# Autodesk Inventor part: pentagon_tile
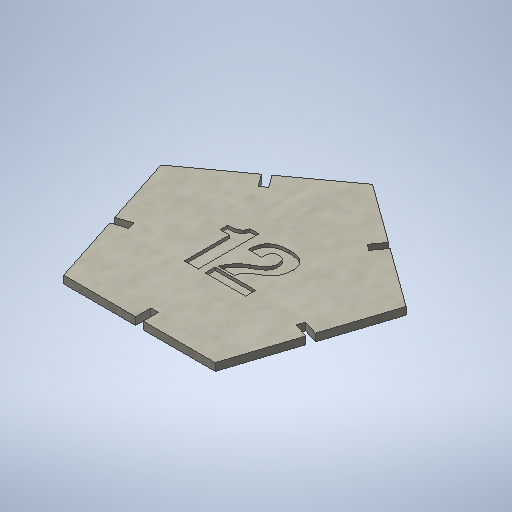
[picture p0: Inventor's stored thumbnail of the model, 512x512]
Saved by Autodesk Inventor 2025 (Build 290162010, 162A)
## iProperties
Created: 2025-02
Part Number: pentagon_tile
Material: Paper
Document SubType Name: Modeling
Designer: BennF
Density: 0.93 g/cm^3
Appearance: Cardboard - Chipboard
Author: BennF
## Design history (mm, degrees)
sketch "Sketch2"
  geometry: L1 (-1.25, -34.41)-(-1.25, -29.41); L2 (-1.25, -29.41)-(1.25, -29.41); L3 (1.25, -29.41)-(1.25, -34.41); L4 (25, -34.41)-(1.25, -34.41); L5 (-1.25, -34.41)-(-25, -34.41); L6 (27.584, -10.277)-(28.356, -7.899); L7 (32.339, -11.822)-(27.584, -10.277); L8 (28.356, -7.899)-(33.112, -9.444); L9 (18.298, 23.058)-(16.275, 24.528); L10 (21.237, 27.103)-(18.298, 23.058); L11 (16.275, 24.528)-(19.214, 28.573); L12 (-16.275, 24.528)-(-18.298, 23.058); L13 (-19.214, 28.573)-(-16.275, 24.528); L14 (-18.298, 23.058)-(-21.237, 27.103); L15 (-28.356, -7.899)-(-27.584, -10.277); L16 (-33.112, -9.444)-(-28.356, -7.899); L17 (-27.584, -10.277)-(-32.339, -11.822); L18 (40.451, 13.143)-(33.112, -9.444); L19 (32.339, -11.822)-(25, -34.41); L20 (0, 42.533)-(19.214, 28.573); L21 (21.237, 27.103)-(40.451, 13.143); L22 (-40.451, 13.143)-(-21.237, 27.103); L23 (-19.214, 28.573)-(0, 42.533); L24 (-25, -34.41)-(-32.339, -11.822); L25 (-33.112, -9.444)-(-40.451, 13.143); 6 further points
  constraints: 50 end point, 3 perpendicular, 2 vertical alignment, 1 collinear, 1 midpoint, 1 vertical, 47 other
  dimensions: "d0" = 50 distance of L4.start L5.end (= pen_side); "d1" = 2.5 distance of L1.end L2.end (= thickness); "d2" = 5 distance of L1.start L1.end (= slot_depth); "d5" = 360 deg dimension on point (0, 0) L1.end (derived)
extrude "Extrusion1" new body sketch "Sketch2" distance "d7" = 2.5 (= thickness); taper "d8" = 0 deg
sketch "Sketch4"
  geometry: L1 (-10, 10)-(10, 10); L2 (10, 10)-(10, -10); L3 (10, -10)-(-10, -10); L4 (-10, -10)-(-10, 10); L5 (-1.25, -29.41)-(1.25, -29.41) reference; 3 further points
  constraints: 2 midpoint, 1 horizontal alignment, 1 parallel, 1 perpendicular, 1 vertical alignment, 2 other
  dimensions: "d9" = 20 distance of L1.start L1.end
emboss "Emboss1" sketch "Sketch4" dims "d10" = 1, "d11" = 0
sketch "laser"
  geometry: L1 (-2.345, -7.041)-(11.013, -7.041) reference; L2 (11.013, -7.041)-(11.013, -10.399) reference; L3 (11.013, -10.399)-(-2.345, -10.399) reference; L4 (-2.345, -10.399)-(-2.345, -7.041) reference; L5 (-7.581, 9.601)-(-4.578, 9.601) reference; L6 (-4.578, 9.601)-(-4.578, -10.399) reference; L7 (-4.578, -10.399)-(-9.149, -10.399) reference; L8 (-9.149, -10.399)-(-9.149, 4.423) reference; L9 (-9.149, 4.423)-(-12.226, 4.423) reference; L10 (-12.226, 4.423)-(-12.226, 6.923) reference; L11 (3.188, -6.317)-(-2.064, -6.317) reference; L12 (2.611, 4.423)-(2.537, 3.388) reference; L13 (2.537, 3.388)-(-1.96, 3.388) reference; L14 (-1.25, -34.41)-(-1.25, -29.41) reference; L15 (-1.25, -29.41)-(1.25, -29.41) reference; L16 (1.25, -29.41)-(1.25, -34.41) reference; L17 (1.25, -34.41)-(25, -34.41) reference; L18 (25, -34.41)-(32.339, -11.822) reference; L19 (32.339, -11.822)-(27.584, -10.277) reference; L20 (27.584, -10.277)-(28.356, -7.899) reference; L21 (28.356, -7.899)-(33.112, -9.444) reference; L22 (33.112, -9.444)-(40.451, 13.143) reference; L23 (40.451, 13.143)-(21.237, 27.103) reference; L24 (21.237, 27.103)-(18.298, 23.058) reference; L25 (18.298, 23.058)-(16.275, 24.528) reference; L26 (16.275, 24.528)-(19.214, 28.573) reference; L27 (19.214, 28.573)-(0, 42.533) reference; L28 (0, 42.533)-(-19.214, 28.573) reference; L29 (-19.214, 28.573)-(-16.275, 24.528) reference; L30 (-16.275, 24.528)-(-18.298, 23.058) reference; L31 (-18.298, 23.058)-(-21.237, 27.103) reference; L32 (-21.237, 27.103)-(-40.451, 13.143) reference; L33 (-40.451, 13.143)-(-33.112, -9.444) reference; L34 (-33.112, -9.444)-(-28.356, -7.899) reference; L35 (-28.356, -7.899)-(-27.584, -10.277) reference; L36 (-27.584, -10.277)-(-32.339, -11.822) reference; L37 (-32.339, -11.822)-(-25, -34.41) reference; L38 (-25, -34.41)-(-1.25, -34.41) reference; 7 further points
  constraints: 9 other
  node "Projected Loop13"
body "Solid1"
node "Sketch Circular Pattern1" dims "d5" = 360 deg (derived)
other parameters: "thickness" = 2.5 [user parameter; used in 2 equation terms], "pen_side" = 50 [user parameter; used in 1 equation term], "clearence" = -0.5 [user parameter], "slot_depth" = 5 [user parameter; used in 1 equation term], "slot_dis_1" = 5 [user parameter], "slot_dis_2" = 12 [user parameter], "slot_clearenece" = 3 [user parameter], "con_angle_1" = 20.34444 [user parameter], "con_angle_2" = 60 deg [user parameter], "con_angle_3" = 12.30959 [user parameter], "con_angle_4" = 19.10633 [user parameter], "con_angle_5" = 24.11865 [user parameter]
